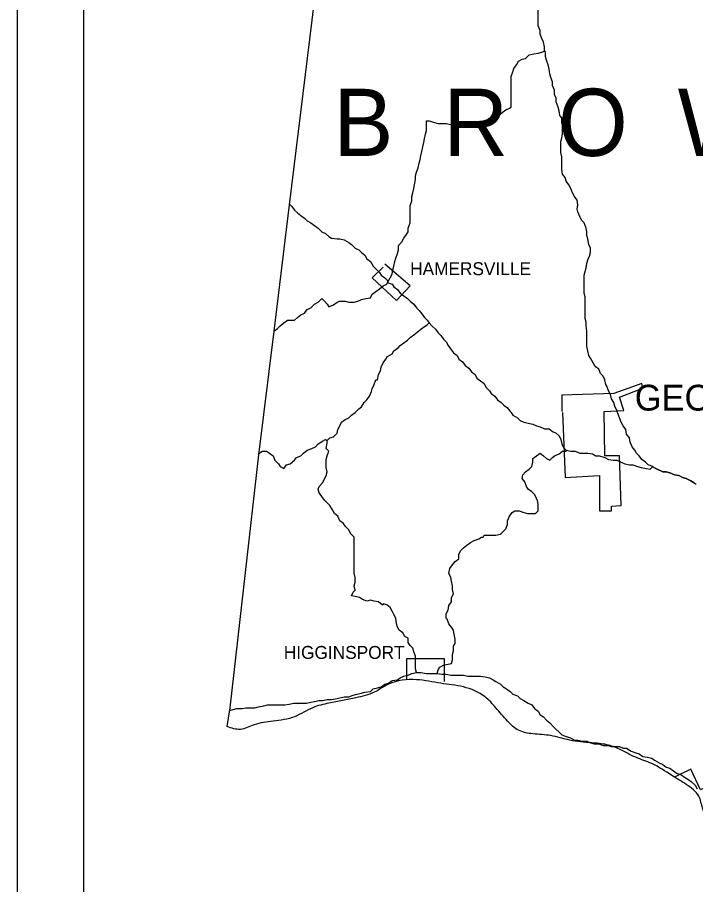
# Model space of a CAD drawing. Extents: x 0 to 34, y 0 to 22.
# Drawn here: x 2 to 3.025, y 16.44 to 17.75 of the extents above; entities that cross this region are included whole.
import ezdxf

# ---------------------------------------------------------------- set-up
doc = ezdxf.new("R2010")
doc.units = 0
for name, color, linetype in [('Default', 7, 'Continuous'), ('SH_Data', 7, 'Continuous'), ('TR_Turning_Path1', 7, 'Continuous')]:
    doc.layers.add(name, color=color, linetype=linetype)

msp = doc.modelspace()

# ---------------------------------------------------------------- linework, layer by layer
at = {"layer": 'Default'}
for points in [[(2.5636, 18.8615), (2.5554, 18.732), (2.5473, 18.6093), (2.535, 18.4934), (2.52, 18.3748), (2.5173, 18.3407), (2.5009, 18.2016), (2.4832, 18.0612), (2.4655, 17.914), (2.4109, 17.4668), (2.3877, 17.2759), (2.3646, 17.0891), (2.3209, 16.7073), (2.3168, 16.6787)], [(2.7968, 17.6999), (2.7968, 17.7054), (2.7954, 17.7122), (2.7927, 17.7176), (2.7899, 17.7245), (2.7899, 17.7299), (2.7872, 17.7367), (2.7872, 17.7435), (2.7872, 17.7504), (2.7872, 17.7572), (2.7872, 17.7626), (2.7886, 17.7694), (2.7899, 17.7749), (2.7899, 17.7817), (2.7899, 17.7899), (2.7899, 17.7953), (2.7899, 17.8022), (2.7954, 17.8076), (2.7981, 17.8131), (2.8022, 17.8185), (2.8049, 17.824), (2.8063, 17.8308), (2.8063, 17.8308)], [(2.7463, 17.6154), (2.7463, 17.6222), (2.7463, 17.6276), (2.7463, 17.6345), (2.7463, 17.6413), (2.7463, 17.6467), (2.7463, 17.6536), (2.7463, 17.6604), (2.749, 17.6672), (2.7504, 17.6726), (2.7545, 17.6781), (2.7572, 17.6835), (2.7627, 17.6863), (2.7681, 17.6876), (2.7736, 17.6931), (2.7804, 17.6945), (2.7872, 17.6958), (2.7927, 17.6972), (2.7968, 17.6985), (2.7968, 17.6999)], [(2.8199, 17.6017), (2.8186, 17.6086), (2.8172, 17.614), (2.8145, 17.6222), (2.8145, 17.6276), (2.8118, 17.6331), (2.8118, 17.6399), (2.809, 17.6467), (2.809, 17.6522), (2.8063, 17.659), (2.8049, 17.6645), (2.8036, 17.6713), (2.8022, 17.6781), (2.7995, 17.6849), (2.7981, 17.6904), (2.7981, 17.6972), (2.7968, 17.6999)], [(2.61, 17.5404), (2.6113, 17.5472), (2.6127, 17.554), (2.6141, 17.5608), (2.6154, 17.5663), (2.6168, 17.5731), (2.6182, 17.5786), (2.6182, 17.5854), (2.6182, 17.5936), (2.6222, 17.5936), (2.6304, 17.5908), (2.6359, 17.5895), (2.6413, 17.5895), (2.6482, 17.5895), (2.655, 17.5881), (2.6618, 17.5867), (2.6672, 17.5867), (2.6741, 17.5867), (2.6809, 17.5854), (2.6863, 17.584), (2.6918, 17.5867), (2.6986, 17.5895), (2.7041, 17.5936), (2.7095, 17.5949), (2.7163, 17.5963), (2.7218, 17.5977), (2.7272, 17.6017), (2.7327, 17.6058), (2.7381, 17.6099), (2.7436, 17.6127), (2.7463, 17.614), (2.7463, 17.6154)], [(2.8213, 17.5486), (2.8213, 17.554), (2.8213, 17.5622), (2.8227, 17.5677), (2.824, 17.5731), (2.824, 17.5786), (2.824, 17.5867), (2.8227, 17.5908), (2.8227, 17.5977), (2.8199, 17.6017)], [(2.8663, 17.3959), (2.8663, 17.4013), (2.8636, 17.4068), (2.8622, 17.415), (2.8608, 17.4204), (2.8608, 17.4259), (2.8595, 17.4313), (2.8568, 17.4395), (2.8527, 17.4436), (2.8499, 17.449), (2.8472, 17.4559), (2.8458, 17.4599), (2.8472, 17.4668), (2.8458, 17.4736), (2.8418, 17.479), (2.839, 17.4845), (2.8363, 17.4913), (2.8336, 17.4968), (2.8295, 17.5022), (2.8281, 17.5077), (2.824, 17.5131), (2.8227, 17.5199), (2.8227, 17.5268), (2.8227, 17.5322), (2.8227, 17.539), (2.8213, 17.5458), (2.8213, 17.5486), (2.8213, 17.5486)], [(2.5595, 17.3495), (2.5636, 17.3563), (2.5663, 17.3618), (2.5677, 17.3686), (2.5691, 17.3741), (2.5704, 17.3809), (2.5718, 17.3863), (2.5745, 17.3931), (2.5759, 17.3986), (2.5759, 17.4054), (2.5813, 17.4109), (2.5841, 17.4163), (2.5882, 17.4218), (2.5909, 17.4259), (2.5909, 17.4313), (2.5936, 17.4395), (2.5936, 17.4463), (2.5936, 17.4518), (2.5936, 17.4586), (2.5936, 17.4654), (2.5963, 17.4722), (2.5963, 17.479), (2.5977, 17.4845), (2.5991, 17.4913), (2.6004, 17.4968), (2.6018, 17.5049), (2.6018, 17.5104), (2.6032, 17.5158), (2.6059, 17.5227), (2.6072, 17.5295), (2.6086, 17.5349), (2.61, 17.5404), (2.61, 17.5404)], [(2.4109, 17.4681), (2.415, 17.464), (2.4191, 17.4586), (2.4232, 17.4545), (2.4286, 17.4504), (2.4341, 17.4463), (2.4382, 17.4422), (2.4436, 17.4395), (2.4491, 17.4354), (2.4545, 17.4313), (2.46, 17.4259), (2.4655, 17.4231), (2.4709, 17.419), (2.475, 17.4163), (2.4832, 17.415), (2.4873, 17.415), (2.4941, 17.4136), (2.5009, 17.4095), (2.505, 17.4068), (2.5104, 17.4013), (2.5159, 17.3986), (2.52, 17.3945), (2.5254, 17.3904), (2.5282, 17.385), (2.5336, 17.3809), (2.5377, 17.3741), (2.5418, 17.37), (2.5473, 17.3645), (2.55, 17.3604), (2.5554, 17.3563), (2.5595, 17.3522), (2.5595, 17.3495)], [(2.4109, 17.4681), (2.415, 17.464), (2.4191, 17.4586), (2.4232, 17.4545), (2.4286, 17.4504), (2.4341, 17.4463), (2.4382, 17.4422), (2.4436, 17.4395), (2.4491, 17.4354), (2.4545, 17.4313), (2.46, 17.4259), (2.4655, 17.4231), (2.4709, 17.419), (2.475, 17.4163), (2.4832, 17.415), (2.4873, 17.415), (2.4941, 17.4136), (2.5009, 17.4095), (2.505, 17.4068), (2.5104, 17.4013), (2.5159, 17.3986), (2.52, 17.3945), (2.5254, 17.3904), (2.5282, 17.385), (2.5336, 17.3809), (2.5377, 17.3741), (2.5418, 17.37), (2.5473, 17.3645), (2.55, 17.3604), (2.5554, 17.3563), (2.5595, 17.3522), (2.5595, 17.3495)], [(2.8581, 17.3141), (2.8581, 17.3195), (2.8581, 17.3277), (2.8568, 17.3331), (2.8568, 17.34), (2.8568, 17.3468), (2.8568, 17.3522), (2.8568, 17.3604), (2.8581, 17.3659), (2.8595, 17.3713), (2.8608, 17.3781), (2.8622, 17.3836), (2.8649, 17.389), (2.8663, 17.3945), (2.8663, 17.3959)], [(2.5527, 17.3727), (2.5364, 17.3563), (2.5732, 17.3222), (2.5936, 17.3441), (2.5554, 17.3768)], [(2.4709, 17.3127), (2.4777, 17.3154), (2.4832, 17.3195), (2.4873, 17.3209), (2.4954, 17.3209), (2.5009, 17.3195), (2.5091, 17.3195), (2.5145, 17.3209), (2.52, 17.3236), (2.5268, 17.325), (2.5336, 17.3263), (2.5364, 17.3318), (2.5418, 17.3359), (2.5473, 17.34), (2.5527, 17.3441), (2.5582, 17.3468), (2.5595, 17.3495), (2.5595, 17.3495)], [(2.5595, 17.3495), (2.5663, 17.3468), (2.5691, 17.3427), (2.5745, 17.3386), (2.5786, 17.3331), (2.5841, 17.3291), (2.5895, 17.325), (2.5936, 17.3209), (2.5991, 17.3168), (2.6032, 17.3113), (2.6072, 17.3072), (2.6113, 17.3018), (2.6154, 17.2963), (2.6195, 17.2922), (2.6222, 17.2882)], [(2.5595, 17.3495), (2.5663, 17.3468), (2.5691, 17.3427), (2.5745, 17.3386), (2.5786, 17.3331), (2.5841, 17.3291), (2.5895, 17.325), (2.5936, 17.3209), (2.5991, 17.3168), (2.6032, 17.3113), (2.6072, 17.3072), (2.6113, 17.3018), (2.6154, 17.2963), (2.6195, 17.2922), (2.6222, 17.2882)], [(2.3877, 17.2759), (2.3932, 17.28), (2.3973, 17.2841), (2.4027, 17.2882), (2.4082, 17.2922), (2.4136, 17.2922), (2.4191, 17.2922), (2.4232, 17.2963), (2.4286, 17.3004), (2.4341, 17.3032), (2.4382, 17.3086), (2.4436, 17.3113), (2.4491, 17.3168), (2.4545, 17.3195), (2.46, 17.325), (2.4641, 17.3209), (2.4682, 17.3168), (2.4709, 17.3127), (2.4709, 17.3127)], [(2.8608, 17.2636), (2.8608, 17.2704), (2.8608, 17.2759), (2.8595, 17.2841), (2.8595, 17.2895), (2.8581, 17.295), (2.8581, 17.3018), (2.8581, 17.3086), (2.8581, 17.3141)], [(2.5445, 17.2023), (2.5459, 17.2104), (2.5486, 17.2159), (2.55, 17.2213), (2.5527, 17.2282), (2.5568, 17.2336), (2.5595, 17.2377), (2.5663, 17.2418), (2.5691, 17.2459), (2.5759, 17.2513), (2.5786, 17.2541), (2.5841, 17.2582), (2.5895, 17.2623), (2.5936, 17.2663), (2.5991, 17.2704), (2.6045, 17.2745), (2.61, 17.2786), (2.6154, 17.2827), (2.6195, 17.2854), (2.6222, 17.2882)], [(2.6222, 17.2882), (2.6263, 17.2841), (2.6318, 17.2786), (2.6359, 17.2732), (2.64, 17.2691), (2.6441, 17.2636), (2.6482, 17.2595), (2.6509, 17.2541), (2.6563, 17.2473), (2.6591, 17.2432), (2.6645, 17.2391), (2.6672, 17.2336), (2.6727, 17.2295), (2.6768, 17.2241), (2.6822, 17.22), (2.6863, 17.2145), (2.6918, 17.2104), (2.6945, 17.205), (2.7, 17.2009), (2.7054, 17.1968), (2.7081, 17.1914), (2.7136, 17.1859), (2.7163, 17.1818), (2.7218, 17.1777), (2.7259, 17.1723), (2.7313, 17.1682), (2.7354, 17.1641), (2.7409, 17.16), (2.745, 17.1545), (2.7463, 17.1532)], [(2.6222, 17.2882), (2.6263, 17.2841), (2.6318, 17.2786), (2.6359, 17.2732), (2.64, 17.2691), (2.6441, 17.2636), (2.6482, 17.2595), (2.6509, 17.2541), (2.6563, 17.2473), (2.6591, 17.2432), (2.6645, 17.2391), (2.6672, 17.2336), (2.6727, 17.2295), (2.6768, 17.2241), (2.6822, 17.22), (2.6863, 17.2145), (2.6918, 17.2104), (2.6945, 17.205), (2.7, 17.2009), (2.7054, 17.1968), (2.7081, 17.1914), (2.7136, 17.1859), (2.7163, 17.1818), (2.7218, 17.1777), (2.7259, 17.1723), (2.7313, 17.1682), (2.7354, 17.1641), (2.7409, 17.16), (2.745, 17.1545), (2.7463, 17.1532)], [(2.8895, 17.1954), (2.8881, 17.2023), (2.8854, 17.2077), (2.8813, 17.2118), (2.8786, 17.2186), (2.8731, 17.2227), (2.8704, 17.2282), (2.8663, 17.235), (2.8636, 17.2391), (2.8622, 17.2459), (2.8608, 17.2527), (2.8608, 17.2582), (2.8608, 17.2636)], [(2.4682, 17.1109), (2.4723, 17.115), (2.4777, 17.1164), (2.4832, 17.1218), (2.4845, 17.1273), (2.4873, 17.1327), (2.49, 17.1382), (2.4954, 17.1423), (2.5009, 17.145), (2.505, 17.1491), (2.5104, 17.1532), (2.5159, 17.1586), (2.52, 17.1614), (2.5241, 17.1682), (2.5282, 17.1723), (2.5323, 17.1777), (2.535, 17.1845), (2.5364, 17.1886), (2.5391, 17.1954), (2.5418, 17.2023), (2.5445, 17.2023)], [(2.824, 17.1532), (2.8281, 17.055), (2.8799, 17.0577), (2.8799, 17.0046), (2.8977, 17.0046), (2.8977, 17.0114), (2.9127, 17.0127), (2.9099, 17.0877), (2.8881, 17.0877), (2.8868, 17.1545), (2.9167, 17.1559), (2.9099, 17.1764), (2.9454, 17.19), (2.944, 17.1968), (2.9017, 17.1818), (2.8227, 17.1791), (2.8227, 17.1545)], [(2.9604, 17.0714), (2.9536, 17.0741), (2.9495, 17.0782), (2.944, 17.0823), (2.9399, 17.0877), (2.9358, 17.0918), (2.9331, 17.0959), (2.929, 17.1014), (2.9263, 17.1082), (2.9249, 17.115), (2.9208, 17.1205), (2.9195, 17.1273), (2.9154, 17.1327), (2.9127, 17.1382), (2.9099, 17.145), (2.9086, 17.1491), (2.9058, 17.1559), (2.9031, 17.1627), (2.9017, 17.1682), (2.8977, 17.1736), (2.8963, 17.1804), (2.8936, 17.1859), (2.8908, 17.1927), (2.8895, 17.1954)], [(2.7463, 17.1532), (2.749, 17.1491), (2.7559, 17.145), (2.76, 17.1409), (2.7654, 17.1382), (2.7722, 17.1368), (2.779, 17.1355), (2.7845, 17.1327), (2.7899, 17.1314), (2.7968, 17.1286), (2.8036, 17.1286), (2.809, 17.1245), (2.8145, 17.1218), (2.8186, 17.1177), (2.8213, 17.1123), (2.8227, 17.1055), (2.8254, 17.1), (2.8295, 17.0959), (2.8295, 17.0959)], [(2.7463, 17.1532), (2.749, 17.1491), (2.7559, 17.145), (2.76, 17.1409), (2.7654, 17.1382), (2.7722, 17.1368), (2.779, 17.1355), (2.7845, 17.1327), (2.7899, 17.1314), (2.7968, 17.1286), (2.8036, 17.1286), (2.809, 17.1245), (2.8145, 17.1218), (2.8186, 17.1177), (2.8213, 17.1123), (2.8227, 17.1055), (2.8254, 17.1), (2.8295, 17.0959), (2.8295, 17.0959)], [(2.3646, 17.0905), (2.37, 17.0946), (2.3768, 17.0946), (2.3809, 17.0918), (2.3864, 17.0877), (2.3891, 17.0809), (2.3946, 17.0755), (2.3973, 17.0714), (2.4027, 17.0686), (2.4068, 17.0741), (2.4123, 17.0755), (2.4191, 17.0809), (2.4218, 17.085), (2.4286, 17.0877), (2.4327, 17.0918), (2.4382, 17.0959), (2.445, 17.0986), (2.4505, 17.1014), (2.4545, 17.1055), (2.4614, 17.1095), (2.4655, 17.1123), (2.4682, 17.1109)], [(2.5091, 16.965), (2.5036, 16.9705), (2.5009, 16.9759), (2.4954, 16.9814), (2.4927, 16.9855), (2.4873, 16.9896), (2.4845, 16.9964), (2.4791, 17.0005), (2.4764, 17.0059), (2.4723, 17.0127), (2.4682, 17.0168), (2.4641, 17.0209), (2.46, 17.0264), (2.4559, 17.0318), (2.4545, 17.0373), (2.4559, 17.0414), (2.4614, 17.0468), (2.4641, 17.0523), (2.4668, 17.0577), (2.4682, 17.0632), (2.4668, 17.07), (2.4668, 17.0755), (2.4668, 17.0823), (2.4682, 17.0877), (2.4709, 17.0946), (2.4668, 17.0986), (2.4682, 17.1068), (2.4682, 17.1082), (2.4682, 17.1109)], [(2.7845, 17.0237), (2.7818, 17.0291), (2.7777, 17.0332), (2.7722, 17.0373), (2.7695, 17.0414), (2.7668, 17.0482), (2.7627, 17.0536), (2.764, 17.0591), (2.7681, 17.0632), (2.7736, 17.0673), (2.7777, 17.0714), (2.779, 17.0782), (2.779, 17.0836), (2.7845, 17.0877), (2.7899, 17.0918), (2.7954, 17.0877), (2.7995, 17.0836), (2.8049, 17.0809), (2.809, 17.085), (2.8118, 17.0877), (2.8186, 17.0905), (2.824, 17.0946), (2.8295, 17.0946), (2.8295, 17.0959)], [(2.8295, 17.0959), (2.8363, 17.0946), (2.8431, 17.0946), (2.8499, 17.0918), (2.8554, 17.0918), (2.8622, 17.0918), (2.869, 17.0905), (2.8745, 17.0877), (2.8799, 17.0877), (2.8881, 17.085), (2.8936, 17.0823), (2.9004, 17.0809), (2.9058, 17.0809), (2.9127, 17.0782), (2.9181, 17.0755), (2.9249, 17.0741), (2.9304, 17.0741), (2.9372, 17.0714), (2.9427, 17.07), (2.9508, 17.0686), (2.9563, 17.0673), (2.959, 17.07), (2.9604, 17.0714)], [(2.8295, 17.0959), (2.8363, 17.0946), (2.8431, 17.0946), (2.8499, 17.0918), (2.8554, 17.0918), (2.8622, 17.0918), (2.869, 17.0905), (2.8745, 17.0877), (2.8799, 17.0877), (2.8881, 17.085), (2.8936, 17.0823), (2.9004, 17.0809), (2.9058, 17.0809), (2.9127, 17.0782), (2.9181, 17.0755), (2.9249, 17.0741), (2.9304, 17.0741), (2.9372, 17.0714), (2.9427, 17.07), (2.9508, 17.0686), (2.9563, 17.0673), (2.959, 17.07), (2.9604, 17.0714)], [(2.9604, 17.0714), (2.9617, 17.07), (2.9672, 17.0673), (2.9754, 17.0632), (2.9808, 17.0632), (2.9863, 17.0618), (2.9931, 17.0591), (2.9999, 17.0577), (3.0054, 17.055), (3.0108, 17.0536), (3.0176, 17.0496), (3.0231, 17.0468)], [(2.9604, 17.0714), (2.9617, 17.07), (2.9672, 17.0673), (2.9754, 17.0632), (2.9808, 17.0632), (2.9863, 17.0618), (2.9931, 17.0591), (2.9999, 17.0577), (3.0054, 17.055), (3.0108, 17.0536), (3.0176, 17.0496), (3.0231, 17.0468)], [(3.0231, 17.0468), (3.0176, 17.0496), (3.0108, 17.0536), (3.0054, 17.055), (2.9999, 17.0577), (2.9931, 17.0591), (2.9863, 17.0618), (2.9808, 17.0632), (2.9754, 17.0632), (2.9672, 17.0673), (2.9617, 17.07), (2.9604, 17.0714)], [(3.0258, 17.0441), (3.0245, 17.0455), (3.0231, 17.0468)], [(2.7054, 16.9678), (2.7109, 16.9678), (2.7163, 16.9678), (2.7231, 16.9678), (2.73, 16.9691), (2.734, 16.9732), (2.7381, 16.9773), (2.7409, 16.9841), (2.7409, 16.9896), (2.7436, 16.9964), (2.7477, 17.0018), (2.7518, 17.0046), (2.7586, 17.0046), (2.7654, 17.0018), (2.7709, 17.0005), (2.7777, 17.0005), (2.7831, 17.0005), (2.7872, 17.0046), (2.7872, 17.0087), (2.7872, 17.0141), (2.7859, 17.0209), (2.7845, 17.0223), (2.7845, 17.0237)], [(2.5513, 16.8628), (2.5459, 16.8669), (2.5391, 16.8682), (2.5336, 16.8696), (2.5282, 16.8682), (2.5214, 16.8709), (2.5173, 16.8737), (2.5104, 16.875), (2.505, 16.8764), (2.5077, 16.8819), (2.5104, 16.8846), (2.5091, 16.8914), (2.5104, 16.8969), (2.5104, 16.9037), (2.5091, 16.9105), (2.5091, 16.9159), (2.5091, 16.9241), (2.5091, 16.9282), (2.5091, 16.935), (2.5091, 16.9432), (2.5091, 16.9487), (2.5091, 16.9568), (2.5091, 16.9637), (2.5091, 16.9637), (2.5091, 16.965)], [(2.6482, 16.8423), (2.6482, 16.8491), (2.6509, 16.8546), (2.6522, 16.8614), (2.6563, 16.8669), (2.6563, 16.8737), (2.6591, 16.8791), (2.6577, 16.8859), (2.6577, 16.8914), (2.6563, 16.8982), (2.655, 16.9037), (2.6522, 16.9105), (2.6536, 16.9173), (2.6577, 16.9228), (2.6618, 16.9282), (2.6672, 16.9323), (2.6672, 16.9391), (2.67, 16.9446), (2.6741, 16.9487), (2.6795, 16.9528), (2.685, 16.9568), (2.6904, 16.9596), (2.6972, 16.9623), (2.7013, 16.965), (2.7041, 16.965), (2.7054, 16.9678)], [(2.6032, 16.7605), (2.6018, 16.766), (2.6018, 16.7728), (2.6018, 16.7796), (2.6018, 16.7851), (2.5991, 16.7919), (2.5977, 16.7973), (2.5936, 16.8014), (2.5909, 16.8055), (2.5909, 16.8123), (2.5854, 16.815), (2.5827, 16.8205), (2.5773, 16.8246), (2.5745, 16.8287), (2.5732, 16.8341), (2.5718, 16.8423), (2.5691, 16.8478), (2.5663, 16.8532), (2.5636, 16.8587), (2.5582, 16.8628), (2.5527, 16.8641), (2.5527, 16.8628), (2.5513, 16.8628)], [(2.6345, 16.7591), (2.6359, 16.7646), (2.6386, 16.7687), (2.6441, 16.7714), (2.6509, 16.7728), (2.6563, 16.7741), (2.6577, 16.7796), (2.6577, 16.7878), (2.6591, 16.7932), (2.6591, 16.8001), (2.6618, 16.8041), (2.6618, 16.811), (2.6604, 16.8178), (2.6591, 16.8246), (2.6563, 16.8287), (2.6522, 16.8341), (2.6495, 16.841), (2.6482, 16.8423)], [(2.6454, 16.7469), (2.6454, 16.781), (2.5882, 16.781), (2.5882, 16.7496)], [(2.3209, 16.7032), (2.3264, 16.7046), (2.3318, 16.706), (2.34, 16.706), (2.3455, 16.7073), (2.3537, 16.7073), (2.3591, 16.7073), (2.3646, 16.7087), (2.3727, 16.7101), (2.3782, 16.7114), (2.3864, 16.7114), (2.3918, 16.7114), (2.3973, 16.7114), (2.4041, 16.7114), (2.4109, 16.7128), (2.4177, 16.7142), (2.4232, 16.7142), (2.43, 16.7142), (2.4368, 16.7142), (2.4436, 16.7155), (2.4491, 16.7169), (2.4559, 16.7182), (2.4614, 16.7182), (2.4682, 16.7196), (2.475, 16.7196), (2.4832, 16.721), (2.4873, 16.7223), (2.4941, 16.7237), (2.5009, 16.7237), (2.5077, 16.7264), (2.5132, 16.7278), (2.52, 16.7292), (2.5254, 16.7305), (2.5336, 16.7319), (2.5377, 16.736), (2.5445, 16.7373), (2.55, 16.7387), (2.5554, 16.7428), (2.5609, 16.7442), (2.5663, 16.7482), (2.5745, 16.7496), (2.5786, 16.7523), (2.5841, 16.7551), (2.5909, 16.7564), (2.5963, 16.7591), (2.6032, 16.7605), (2.6032, 16.7605)], [(2.6032, 16.7605), (2.61, 16.7605), (2.6182, 16.7591), (2.625, 16.7591), (2.6304, 16.7591), (2.6345, 16.7591)], [(2.6345, 16.7591), (2.6413, 16.7578), (2.6482, 16.7578), (2.655, 16.7564), (2.6618, 16.7564), (2.6672, 16.7564), (2.6741, 16.7564), (2.6809, 16.7551), (2.6863, 16.7551), (2.6931, 16.7551), (2.7, 16.7551), (2.7068, 16.7537), (2.7136, 16.7523), (2.719, 16.7496), (2.7231, 16.7469), (2.73, 16.7428), (2.734, 16.7387), (2.7395, 16.736), (2.745, 16.7319), (2.749, 16.7278), (2.7559, 16.7251), (2.7559, 16.7251)], [(2.7559, 16.7251), (2.76, 16.721), (2.7654, 16.7182), (2.7722, 16.7142), (2.7777, 16.7114), (2.7818, 16.706), (2.7872, 16.7019), (2.7899, 16.6964), (2.7954, 16.6937), (2.7995, 16.6883), (2.8049, 16.6842), (2.809, 16.6801), (2.8145, 16.6746), (2.8186, 16.6705), (2.8227, 16.6664), (2.8295, 16.6637), (2.8349, 16.6623), (2.8418, 16.6583), (2.8472, 16.6583), (2.854, 16.6569), (2.8608, 16.6569), (2.8663, 16.6542), (2.8718, 16.6528), (2.8786, 16.6528), (2.8854, 16.6501), (2.8922, 16.6501), (2.8977, 16.6487), (2.9045, 16.6487), (2.9099, 16.6487), (2.9154, 16.646)], [(2.9154, 16.646), (2.9208, 16.646), (2.9277, 16.6419), (2.9345, 16.6392), (2.9399, 16.6378), (2.9454, 16.6337), (2.9522, 16.6324), (2.959, 16.631), (2.9631, 16.6283), (2.9699, 16.6242), (2.9754, 16.6214), (2.9808, 16.6174), (2.9863, 16.616), (2.9917, 16.6119), (2.9972, 16.6078), (3.0026, 16.6064), (3.0081, 16.6024), (3.0135, 16.5996), (3.019, 16.5955), (3.0245, 16.5901), (3.0272, 16.5846)], [(3.0626, 16.4524), (3.1172, 16.4796), (3.0735, 16.571), (3.1008, 16.5833), (3.0899, 16.6119), (3.0326, 16.5833), (3.0176, 16.6146), (2.9931, 16.6024)]]:
    msp.add_lwpolyline(points, dxfattribs=at)
msp.add_spline([(3.5398, 16.0652), (3.5194, 16.0652), (3.5126, 16.0733), (3.4989, 16.0761), (3.4935, 16.0856), (3.4853, 16.0924), (3.4717, 16.0924), (3.4498, 16.1006), (3.428, 16.0979), (3.3953, 16.1047), (3.3667, 16.1143), (3.3394, 16.1183), (3.323, 16.1252), (3.3094, 16.1347), (3.3026, 16.147), (3.289, 16.1702), (3.2876, 16.1961), (3.2835, 16.2233), (3.2767, 16.2451), (3.274, 16.2765), (3.2671, 16.3106), (3.2562, 16.331), (3.2399, 16.346), (3.2208, 16.3597), (3.2044, 16.3665), (3.1799, 16.3747), (3.1499, 16.3774), (3.1267, 16.3856), (3.1131, 16.3951), (3.094, 16.4088), (3.0776, 16.4197), (3.064, 16.436), (3.0572, 16.4578), (3.0572, 16.4783), (3.0504, 16.4987), (3.0435, 16.5328), (3.0354, 16.556), (3.0299, 16.5737), (3.0108, 16.5914), (2.989, 16.6051), (2.959, 16.6228), (2.9345, 16.6324), (2.9099, 16.6446), (2.8908, 16.6514), (2.8677, 16.6542), (2.8349, 16.6583), (2.8063, 16.6651), (2.779, 16.6678), (2.7572, 16.6733), (2.7409, 16.6869), (2.7231, 16.7073), (2.7068, 16.7237), (2.6741, 16.7387), (2.64, 16.7442), (2.6032, 16.7496), (2.5609, 16.7428), (2.5391, 16.7305), (2.5118, 16.7223), (2.4709, 16.7142), (2.4464, 16.7073), (2.4191, 16.6937), (2.3864, 16.6869), (2.3577, 16.6814), (2.3373, 16.6746), (2.3168, 16.6787)], degree=3, dxfattribs=at)
at = {"layer": 'SH_Data'}
for p, q in [((2, 21), (2, 14)), ((2.1, 20.9), (2.1, 14.1))]:
    msp.add_line(p, q, dxfattribs=at)

# ---------------------------------------------------------------- texts
at = {"layer": 'Default'}
for s, height, p in [('HAMERSVILLE', 0.019502, (2.5936, 17.3604)), ('GEORGETOWN', 0.039, (2.9331, 17.1559)), ('HIGGINSPORT', 0.019502, (2.4027, 16.781))]:
    msp.add_text(s, height=height, dxfattribs=at).set_placement(p)
at = {"layer": 'TR_Turning_Path1'}
msp.add_text('B  R  O  W  N', height=0.101489, dxfattribs=at).set_placement((2.4777, 17.5404))

doc.saveas('drawing.dxf')
